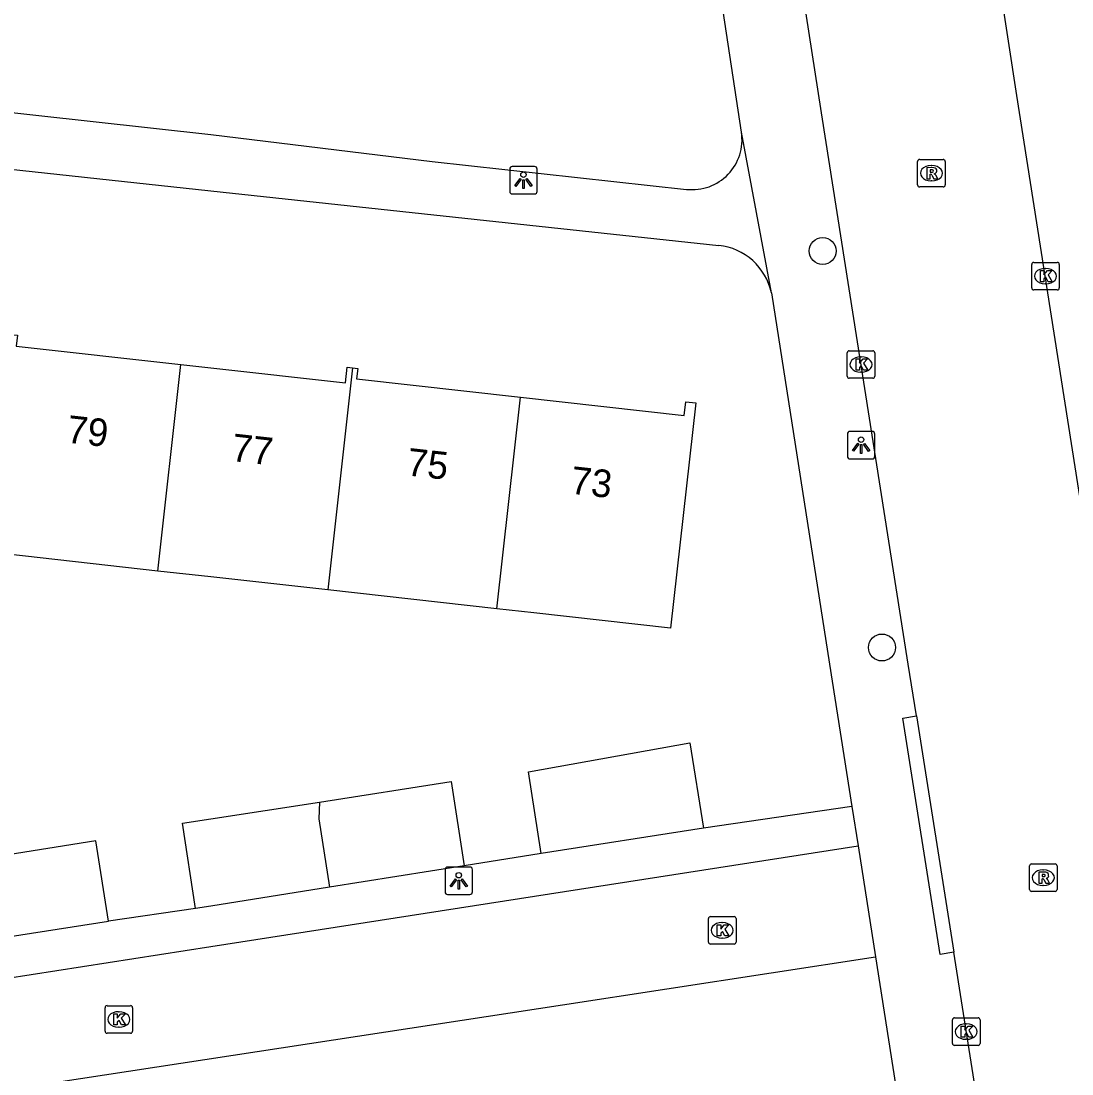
# Model space of a CAD drawing. Extents: x 162026 to 163499, y 387297 to 388169.
# Drawn here: x 162493.11 to 162531.25, y 387485.13 to 387523.33 of the extents above; entities that cross this region are included whole.
import ezdxf

# ---------------------------------------------------------------- set-up
doc = ezdxf.new("R2010")
doc.units = 0
for name, color, linetype in [('IMGEO_Boom', 7, 'Continuous'), ('IMGEO_Kolk', 7, 'Continuous'), ('IMGEO_Lichtpunt', 7, 'Continuous'), ('IMGEO_Muur', 7, 'Continuous'), ('IMGEO_Pand', 7, 'Continuous'), ('IMGEO_Pand_nummerreeks', 7, 'Continuous'), ('IMGEO_Rijbaan_lokaal_open', 7, 'Continuous'), ('IMGEO_Rioolput', 7, 'Continuous'), ('IMGEO_Voetpad_open', 7, 'Continuous')]:
    doc.layers.add(name, color=color, linetype=linetype)

msp = doc.modelspace()

# ---------------------------------------------------------------- linework, layer by layer
at = {"layer": 'IMGEO_Boom'}
for centre in [(162522.206, 387514.991), (162524.357, 387500.602)]:
    msp.add_circle(centre, 0.489, dxfattribs=at)
at = {"layer": 'IMGEO_Kolk'}
for p, q in [((162529.793, 387513.651), (162529.793, 387514.503)), ((162529.868, 387514.577), (162530.72, 387514.577)), ((162530.794, 387514.503), (162530.794, 387513.651)), ((162530.281, 387514.357), (162530.306, 387514.357)), ((162530.304, 387513.797), (162530.279, 387513.797)), ((162530.72, 387513.577), (162529.868, 387513.577)), ((162523.172, 387511.371), (162524.024, 387511.371)), ((162523.097, 387510.445), (162523.097, 387511.297)), ((162523.585, 387511.151), (162523.61, 387511.151)), ((162524.098, 387511.297), (162524.098, 387510.445)), ((162523.608, 387510.591), (162523.583, 387510.591)), ((162524.024, 387510.371), (162523.172, 387510.371)), ((162518.061, 387489.912), (162518.061, 387490.764)), ((162518.136, 387490.838), (162518.988, 387490.838)), ((162519.062, 387490.764), (162519.062, 387489.912)), ((162518.549, 387490.618), (162518.574, 387490.618)), ((162518.572, 387490.058), (162518.547, 387490.058)), ((162518.988, 387489.838), (162518.136, 387489.838)), ((162496.159, 387486.679), (162496.159, 387487.531)), ((162496.234, 387487.605), (162497.086, 387487.605)), ((162496.647, 387487.385), (162496.672, 387487.385)), ((162497.16, 387487.531), (162497.16, 387486.679)), ((162526.917, 387486.238), (162526.917, 387487.09)), ((162526.992, 387487.164), (162527.844, 387487.164)), ((162527.405, 387486.944), (162527.43, 387486.944)), ((162527.918, 387487.09), (162527.918, 387486.238)), ((162497.086, 387486.605), (162496.234, 387486.605)), ((162496.67, 387486.825), (162496.645, 387486.825)), ((162527.844, 387486.164), (162526.992, 387486.164)), ((162527.428, 387486.384), (162527.403, 387486.384))]:
    msp.add_line(p, q, dxfattribs=at)
for points in [[(162529.793, 387513.651), (162529.793, 387514.503)], [(162529.868, 387514.577), (162530.72, 387514.577)], [(162530.794, 387514.503), (162530.794, 387513.651)], [(162530.114, 387514.277), (162530.237, 387514.277), (162530.237, 387514.126), (162530.367, 387514.277), (162530.531, 387514.277), (162530.385, 387514.126), (162530.538, 387513.877), (162530.386, 387513.877), (162530.301, 387514.041), (162530.237, 387513.974), (162530.237, 387513.877), (162530.114, 387513.877), (162530.114, 387514.277)], [(162530.72, 387513.577), (162529.868, 387513.577)], [(162523.172, 387511.371), (162524.024, 387511.371)], [(162523.097, 387510.445), (162523.097, 387511.297)], [(162523.418, 387511.071), (162523.541, 387511.071), (162523.541, 387510.92), (162523.671, 387511.071), (162523.835, 387511.071), (162523.689, 387510.92), (162523.842, 387510.671), (162523.69, 387510.671), (162523.605, 387510.835), (162523.541, 387510.768), (162523.541, 387510.671), (162523.418, 387510.671), (162523.418, 387511.071)], [(162524.098, 387511.297), (162524.098, 387510.445)], [(162524.024, 387510.371), (162523.172, 387510.371)], [(162518.061, 387489.912), (162518.061, 387490.764)], [(162518.136, 387490.838), (162518.988, 387490.838)], [(162519.062, 387490.764), (162519.062, 387489.912)], [(162518.382, 387490.538), (162518.505, 387490.538), (162518.505, 387490.387), (162518.635, 387490.538), (162518.799, 387490.538), (162518.653, 387490.387), (162518.806, 387490.138), (162518.654, 387490.138), (162518.569, 387490.302), (162518.505, 387490.235), (162518.505, 387490.138), (162518.382, 387490.138), (162518.382, 387490.538)], [(162518.988, 387489.838), (162518.136, 387489.838)], [(162496.159, 387486.679), (162496.159, 387487.531)], [(162496.234, 387487.605), (162497.086, 387487.605)], [(162496.48, 387487.305), (162496.603, 387487.305), (162496.603, 387487.154), (162496.733, 387487.305), (162496.897, 387487.305), (162496.751, 387487.154), (162496.904, 387486.905), (162496.752, 387486.905), (162496.667, 387487.069), (162496.603, 387487.002), (162496.603, 387486.905), (162496.48, 387486.905), (162496.48, 387487.305)], [(162497.16, 387487.531), (162497.16, 387486.679)], [(162526.917, 387486.238), (162526.917, 387487.09)], [(162526.992, 387487.164), (162527.844, 387487.164)], [(162527.918, 387487.09), (162527.918, 387486.238)], [(162497.086, 387486.605), (162496.234, 387486.605)], [(162527.238, 387486.864), (162527.361, 387486.864), (162527.361, 387486.713), (162527.491, 387486.864), (162527.655, 387486.864), (162527.509, 387486.713), (162527.662, 387486.464), (162527.51, 387486.464), (162527.425, 387486.628), (162527.361, 387486.561), (162527.361, 387486.464), (162527.238, 387486.464), (162527.238, 387486.864)], [(162527.844, 387486.164), (162526.992, 387486.164)]]:
    msp.add_lwpolyline(points, dxfattribs=at)
for centre, start, end in [((162529.87, 387514.501), 91.552, 178.448), ((162529.87, 387514.501), 91.552, 178.448), ((162530.718, 387514.501), 1.552, 88.448), ((162530.718, 387514.501), 1.552, 88.448), ((162529.87, 387513.653), 181.552, 268.448), ((162529.87, 387513.653), 181.552, 268.448), ((162530.718, 387513.653), 271.552, 358.448), ((162530.718, 387513.653), 271.552, 358.448), ((162523.174, 387511.295), 91.552, 178.448), ((162523.174, 387511.295), 91.552, 178.448), ((162524.022, 387511.295), 1.552, 88.448), ((162524.022, 387511.295), 1.552, 88.448), ((162523.174, 387510.447), 181.552, 268.448), ((162523.174, 387510.447), 181.552, 268.448), ((162524.022, 387510.447), 271.552, 358.448), ((162524.022, 387510.447), 271.552, 358.448), ((162518.138, 387490.762), 91.552, 178.448), ((162518.138, 387490.762), 91.552, 178.448), ((162518.986, 387490.762), 1.552, 88.448), ((162518.986, 387490.762), 1.552, 88.448), ((162518.138, 387489.914), 181.552, 268.448), ((162518.138, 387489.914), 181.552, 268.448), ((162518.986, 387489.914), 271.552, 358.448), ((162518.986, 387489.914), 271.552, 358.448), ((162496.236, 387487.529), 91.552, 178.448), ((162496.236, 387487.529), 91.552, 178.448), ((162497.084, 387487.529), 1.552, 88.448), ((162497.084, 387487.529), 1.552, 88.448), ((162526.994, 387487.088), 91.552, 178.448), ((162526.994, 387487.088), 91.552, 178.448), ((162527.842, 387487.088), 1.552, 88.448), ((162527.842, 387487.088), 1.552, 88.448), ((162496.236, 387486.681), 181.552, 268.448), ((162496.236, 387486.681), 181.552, 268.448), ((162497.084, 387486.681), 271.552, 358.448), ((162497.084, 387486.681), 271.552, 358.448), ((162526.994, 387486.24), 181.552, 268.448), ((162526.994, 387486.24), 181.552, 268.448), ((162527.842, 387486.24), 271.552, 358.448), ((162527.842, 387486.24), 271.552, 358.448)]:
    msp.add_arc(centre, 0.0765, start, end, dxfattribs=at)
for centre, major_axis, ratio, start_param, end_param in [((162530.28, 387514.077), (-0.387, 0.002), 0.722429, 4.712389, 7.853982), ((162530.305, 387514.077), (-0.39, 0.002), 0.717154, 1.570796, 4.712389), ((162523.584, 387510.871), (-0.387, 0.002), 0.722429, 4.712389, 7.853982), ((162523.609, 387510.871), (-0.39, 0.002), 0.717154, 1.570796, 4.712389), ((162518.548, 387490.338), (-0.387, 0.002), 0.722429, 4.712389, 7.853982), ((162518.573, 387490.338), (-0.39, 0.002), 0.717154, 1.570796, 4.712389), ((162496.646, 387487.105), (-0.387, 0.002), 0.722429, 4.712389, 7.853982), ((162496.671, 387487.105), (-0.39, 0.002), 0.717154, 1.570796, 4.712389), ((162527.404, 387486.664), (-0.387, 0.002), 0.722429, 4.712389, 7.853982), ((162527.429, 387486.664), (-0.39, 0.002), 0.717154, 1.570796, 4.712389)]:
    msp.add_ellipse(centre, major_axis=major_axis, ratio=ratio, start_param=start_param, end_param=end_param, dxfattribs=at)
at = {"layer": 'IMGEO_Lichtpunt'}
for p, q in [((162510.847, 387517.962), (162510.847, 387517.155)), ((162510.847, 387517.962), (162510.847, 387517.155)), ((162511.749, 387518.057), (162510.941, 387518.057)), ((162511.749, 387518.057), (162510.941, 387518.057)), ((162511.843, 387517.155), (162511.843, 387517.962)), ((162511.843, 387517.155), (162511.843, 387517.962)), ((162510.941, 387517.061), (162511.749, 387517.061)), ((162510.941, 387517.061), (162511.749, 387517.061)), ((162523.103, 387508.347), (162523.103, 387507.54)), ((162523.103, 387508.347), (162523.103, 387507.54)), ((162524.005, 387508.442), (162523.197, 387508.442)), ((162524.005, 387508.442), (162523.197, 387508.442)), ((162524.099, 387507.54), (162524.099, 387508.347)), ((162524.099, 387507.54), (162524.099, 387508.347)), ((162523.197, 387507.446), (162524.005, 387507.446)), ((162523.197, 387507.446), (162524.005, 387507.446)), ((162509.403, 387492.635), (162508.595, 387492.635)), ((162509.403, 387492.635), (162508.595, 387492.635)), ((162508.501, 387492.54), (162508.501, 387491.733)), ((162508.501, 387492.54), (162508.501, 387491.733)), ((162509.497, 387491.733), (162509.497, 387492.54)), ((162509.497, 387491.733), (162509.497, 387492.54)), ((162508.595, 387491.639), (162509.403, 387491.639)), ((162508.595, 387491.639), (162509.403, 387491.639))]:
    msp.add_line(p, q, dxfattribs=at)
for points in [[(162511.221, 387517.626), (162511.26, 387517.598), (162511.072, 387517.336), (162511.034, 387517.363), (162511.221, 387517.626)], [(162511.323, 387517.578), (162511.37, 387517.578), (162511.37, 387517.256), (162511.323, 387517.256), (162511.323, 387517.578)], [(162511.433, 387517.598), (162511.471, 387517.625), (162511.658, 387517.363), (162511.619, 387517.335), (162511.433, 387517.598)], [(162523.477, 387508.011), (162523.516, 387507.983), (162523.328, 387507.721), (162523.29, 387507.748), (162523.477, 387508.011)], [(162523.579, 387507.963), (162523.626, 387507.963), (162523.626, 387507.641), (162523.579, 387507.641), (162523.579, 387507.963)], [(162523.689, 387507.983), (162523.727, 387508.01), (162523.914, 387507.748), (162523.875, 387507.72), (162523.689, 387507.983)], [(162508.875, 387492.204), (162508.914, 387492.176), (162508.726, 387491.914), (162508.688, 387491.941), (162508.875, 387492.204)], [(162508.977, 387492.156), (162509.024, 387492.156), (162509.024, 387491.834), (162508.977, 387491.834), (162508.977, 387492.156)], [(162509.087, 387492.176), (162509.125, 387492.203), (162509.312, 387491.941), (162509.273, 387491.913), (162509.087, 387492.176)]]:
    msp.add_lwpolyline(points, dxfattribs=at)
for centre in [(162511.346, 387517.76), (162523.602, 387508.145), (162509, 387492.338)]:
    msp.add_circle(centre, 0.0994, dxfattribs=at)
for centre, start, end in [((162510.941, 387517.962), 90, 180), ((162510.941, 387517.962), 90, 180), ((162511.749, 387517.962), 0, 90), ((162511.749, 387517.962), 0, 90), ((162510.941, 387517.155), 180, 270), ((162510.941, 387517.155), 180, 270), ((162511.749, 387517.155), 270, 0), ((162511.749, 387517.155), 270, 360), ((162523.197, 387508.347), 90, 180), ((162523.197, 387508.347), 90, 180), ((162524.005, 387508.347), 0, 90), ((162524.005, 387508.347), 0, 90), ((162523.197, 387507.54), 180, 270), ((162523.197, 387507.54), 180, 270), ((162524.005, 387507.54), 270, 0), ((162524.005, 387507.54), 270, 360), ((162508.595, 387492.54), 90, 180), ((162508.595, 387492.54), 90, 180), ((162509.403, 387492.54), 0, 90), ((162509.403, 387492.54), 0, 90), ((162508.595, 387491.733), 180, 270), ((162508.595, 387491.733), 180, 270), ((162509.403, 387491.733), 270, 0), ((162509.403, 387491.733), 270, 360)]:
    msp.add_arc(centre, 0.0946, start, end, dxfattribs=at)
at = {"layer": 'IMGEO_Muur'}
for points in [[(162512.763, 387487.637), (162524.125, 387489.378)], [(162524.125, 387489.378), (162525.641, 387479.724)], [(162493.374, 387484.666), (162512.763, 387487.637)]]:
    msp.add_lwpolyline(points, dxfattribs=at)
at = {"layer": 'IMGEO_Pand'}
for points in [[(162492.85, 387511.945), (162492.978, 387511.931), (162492.934, 387511.542), (162498.912, 387510.875)], [(162498.081, 387503.377), (162498.912, 387510.875)], [(162498.912, 387510.875), (162500, 387510.754), (162504.89, 387510.209), (162504.952, 387510.769), (162505.14, 387510.748)], [(162505.14, 387510.748), (162504.247, 387502.69)], [(162505.14, 387510.748), (162505.332, 387510.727), (162505.29, 387510.35), (162511.235, 387509.687)], [(162511.235, 387509.687), (162517.179, 387509.025), (162517.234, 387509.517), (162517.598, 387509.476), (162516.687, 387501.303), (162511.718, 387501.857), (162510.383, 387502.006)], [(162510.383, 387502.006), (162511.235, 387509.687)], [(162498.081, 387503.377), (162491.976, 387504.058)], [(162504.247, 387502.69), (162500, 387503.163), (162498.081, 387503.377)], [(162510.383, 387502.006), (162504.247, 387502.69)], [(162511.984, 387493.124), (162511.529, 387496.09), (162517.383, 387497.139), (162517.877, 387494.046)], [(162503.941, 387494.993), (162508.726, 387495.734), (162509.191, 387492.68)], [(162499.445, 387491.132), (162498.967, 387494.223), (162500, 387494.383), (162503.941, 387494.993)], [(162503.941, 387494.993), (162503.917, 387494.384), (162504.303, 387491.903)], [(162517.877, 387494.046), (162511.984, 387493.124)], [(162496.288, 387490.668), (162495.823, 387493.581), (162490.891, 387492.799)], [(162509.191, 387492.68), (162504.303, 387491.903)], [(162504.303, 387491.903), (162500, 387491.22), (162499.445, 387491.132)], [(162491.233, 387489.88), (162496.288, 387490.668)]]:
    msp.add_lwpolyline(points, dxfattribs=at)
at = {"layer": 'IMGEO_Rijbaan_lokaal_open'}
for points in [[(162533.685, 387492.451), (162532.501, 387500), (162529.25, 387520.63), (162527.396, 387532.789)], [(162525.611, 387498.118), (162525.314, 387500), (162522.168, 387520.003), (162520.243, 387532.419)], [(162525.611, 387498.118), (162526.965, 387489.545)], [(162459.001, 387483.37), (162500, 387489.751), (162523.492, 387493.408)], [(162523.492, 387493.408), (162524.125, 387489.378)], [(162493.374, 387484.666), (162512.763, 387487.637), (162524.125, 387489.378)], [(162528.395, 387480.484), (162526.965, 387489.545)]]:
    msp.add_lwpolyline(points, dxfattribs=at)
at = {"layer": 'IMGEO_Rioolput'}
for p, q in [((162525.652, 387517.388), (162525.652, 387518.24)), ((162525.727, 387518.314), (162526.579, 387518.314)), ((162526.653, 387518.24), (162526.653, 387517.388)), ((162526.14, 387518.094), (162526.165, 387518.094)), ((162526.163, 387517.534), (162526.138, 387517.534)), ((162526.579, 387517.314), (162525.727, 387517.314)), ((162529.713, 387491.823), (162529.713, 387492.675)), ((162529.788, 387492.749), (162530.64, 387492.749)), ((162530.714, 387492.675), (162530.714, 387491.823)), ((162530.201, 387492.529), (162530.226, 387492.529)), ((162530.224, 387491.969), (162530.199, 387491.969)), ((162530.64, 387491.749), (162529.788, 387491.749))]:
    msp.add_line(p, q, dxfattribs=at)
for points in [[(162525.652, 387517.388), (162525.652, 387518.24)], [(162525.727, 387518.314), (162526.579, 387518.314)], [(162526.653, 387518.24), (162526.653, 387517.388)], [(162526.241, 387518.012), (162525.989, 387518.014), (162525.989, 387517.614)], [(162526.167, 387517.933), (162526.113, 387517.933), (162526.113, 387517.852)], [(162526.113, 387517.852), (162526.165, 387517.852)], [(162525.989, 387517.614), (162526.113, 387517.614), (162526.113, 387517.776), (162526.124, 387517.776)], [(162526.171, 387517.747), (162526.242, 387517.614), (162526.382, 387517.614), (162526.317, 387517.74)], [(162526.579, 387517.314), (162525.727, 387517.314)], [(162529.713, 387491.823), (162529.713, 387492.675)], [(162529.788, 387492.749), (162530.64, 387492.749)], [(162530.714, 387492.675), (162530.714, 387491.823)], [(162530.302, 387492.447), (162530.05, 387492.449), (162530.05, 387492.049)], [(162530.228, 387492.368), (162530.174, 387492.368), (162530.174, 387492.287)], [(162530.174, 387492.287), (162530.226, 387492.287)], [(162530.05, 387492.049), (162530.174, 387492.049), (162530.174, 387492.211), (162530.185, 387492.211)], [(162530.232, 387492.182), (162530.303, 387492.049), (162530.443, 387492.049), (162530.378, 387492.175)], [(162530.64, 387491.749), (162529.788, 387491.749)]]:
    msp.add_lwpolyline(points, dxfattribs=at)
for centre, radius, start, end in [((162525.729, 387518.238), 0.0765, 91.552, 178.448), ((162525.729, 387518.238), 0.0765, 91.552, 178.448), ((162526.577, 387518.238), 0.0765, 1.552, 88.448), ((162526.577, 387518.238), 0.0765, 1.552, 88.448), ((162526.149, 387518.041), 0.19, 274.7715, 282.9687), ((162526.173, 387517.837), 0.0964, 77.0061, 93.1865), ((162526.187, 387517.894), 0.0378, 276.6634, 79.6772), ((162526.24, 387517.902), 0.109, 350.3612, 89.416), ((162526.238, 387517.902), 0.112, 277.5842, 350.9817), ((162526.123, 387517.723), 0.0533, 26.0293, 88.6989), ((162526.222, 387517.687), 0.108, 29.5134, 73.7905), ((162525.729, 387517.39), 0.0765, 181.552, 268.448), ((162525.729, 387517.39), 0.0765, 181.552, 268.448), ((162526.577, 387517.39), 0.0765, 271.552, 358.448), ((162526.577, 387517.39), 0.0765, 271.552, 358.448), ((162529.79, 387492.673), 0.0765, 91.552, 178.448), ((162529.79, 387492.673), 0.0765, 91.552, 178.448), ((162530.638, 387492.673), 0.0765, 1.552, 88.448), ((162530.638, 387492.673), 0.0765, 1.552, 88.448), ((162530.21, 387492.476), 0.19, 274.7715, 282.9687), ((162530.234, 387492.272), 0.0964, 77.0061, 93.1865), ((162530.248, 387492.329), 0.0378, 276.6634, 79.6772), ((162530.301, 387492.337), 0.109, 350.3612, 89.416), ((162530.299, 387492.337), 0.112, 277.5842, 350.9817), ((162530.184, 387492.158), 0.0533, 26.0293, 88.6989), ((162530.283, 387492.122), 0.108, 29.5134, 73.7905), ((162529.79, 387491.825), 0.0765, 181.552, 268.448), ((162529.79, 387491.825), 0.0765, 181.552, 268.448), ((162530.638, 387491.825), 0.0765, 271.552, 358.448), ((162530.638, 387491.825), 0.0765, 271.552, 358.448)]:
    msp.add_arc(centre, radius, start, end, dxfattribs=at)
for centre, major_axis, ratio, start_param, end_param in [((162526.139, 387517.814), (-0.387, 0.002), 0.722429, 4.712389, 7.853982), ((162526.164, 387517.814), (-0.39, 0.002), 0.717154, 1.570796, 4.712389), ((162530.2, 387492.249), (-0.387, 0.002), 0.722429, 4.712389, 7.853982), ((162530.225, 387492.249), (-0.39, 0.002), 0.717154, 1.570796, 4.712389)]:
    msp.add_ellipse(centre, major_axis=major_axis, ratio=ratio, start_param=start_param, end_param=end_param, dxfattribs=at)
at = {"layer": 'IMGEO_Voetpad_open'}
for points in [[(162519.258, 387519.297), (162518.476, 387524.504), (162517.921, 387527.627), (162517.307, 387531.788)], [(162483.01, 387521.095), (162500, 387519.218), (162508.036, 387518.243), (162517.269, 387517.227)], [(162480.419, 387513.193), (162481.197, 387519.204), (162500, 387517.178), (162518.432, 387515.192)], [(162520.344, 387513.473), (162519.258, 387519.297)], [(162520.344, 387513.473), (162522.459, 387500), (162523.269, 387494.83)], [(162526.965, 387489.545), (162526.472, 387489.464), (162525.119, 387498.037), (162525.611, 387498.118)], [(162523.269, 387494.83), (162517.877, 387494.046)], [(162523.269, 387494.83), (162523.492, 387493.408)], [(162511.984, 387493.124), (162509.191, 387492.68)], [(162499.445, 387491.132), (162496.288, 387490.668)], [(162524.125, 387489.378), (162525.641, 387479.724), (162527.764, 387466.21)]]:
    msp.add_lwpolyline(points, dxfattribs=at)
for centre, radius, start, end in [((162517.468, 387519.027), 1.811, 263.7044, 8.582), ((162518.199, 387513.01), 2.194, 12.1784, 83.9068)]:
    msp.add_arc(centre, radius, start, end, dxfattribs=at)

# ---------------------------------------------------------------- texts
at = {"layer": 'IMGEO_Pand_nummerreeks'}
for s, rotation, p in [('79', 353.6335, (162494.738, 387508.04)), ('77', 353.643, (162500.717, 387507.374)), ('75', 353.6461, (162507.079, 387506.851)), ('73', 353.6355, (162513.023, 387506.188))]:
    msp.add_text(s, height=1, rotation=rotation, dxfattribs=at).set_placement(p)

doc.saveas('drawing.dxf')
